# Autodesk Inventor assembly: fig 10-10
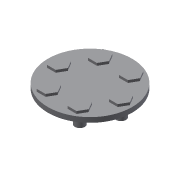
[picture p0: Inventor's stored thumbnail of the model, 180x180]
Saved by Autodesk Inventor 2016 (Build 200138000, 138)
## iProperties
Created: 2008-05
Part Number: fig 10-10
Document SubType Name: Assembly
Designer: CADCIM
Author: CADCIM
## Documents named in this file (3)
- D:\KAVITA\Autodesk Inventor_ 2016 Project_Kavita\Inventor_Part Files\Inventor_2016_Part\c10_Inv_2016\c10_inv_2016_prt\fig 10-10.iam
- D:\KAVITA\Autodesk Inventor_ 2016 Project_Kavita\Inventor_Part Files\Inventor_2016_Part\c10_Inv_2016\c10_inv_2016_prt\Part4.ipt
- D:\KAVITA\Autodesk Inventor_ 2016 Project_Kavita\Inventor_Part Files\Inventor_2016_Part\c10_Inv_2016\c10_inv_2016_prt\Part5.ipt
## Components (7 placed, 2 different names)
1. Part4:1
2. Part5:1
3. Part5:2
4. Part5:3
5. Part5:4
6. Part5:5
7. Part5:6
